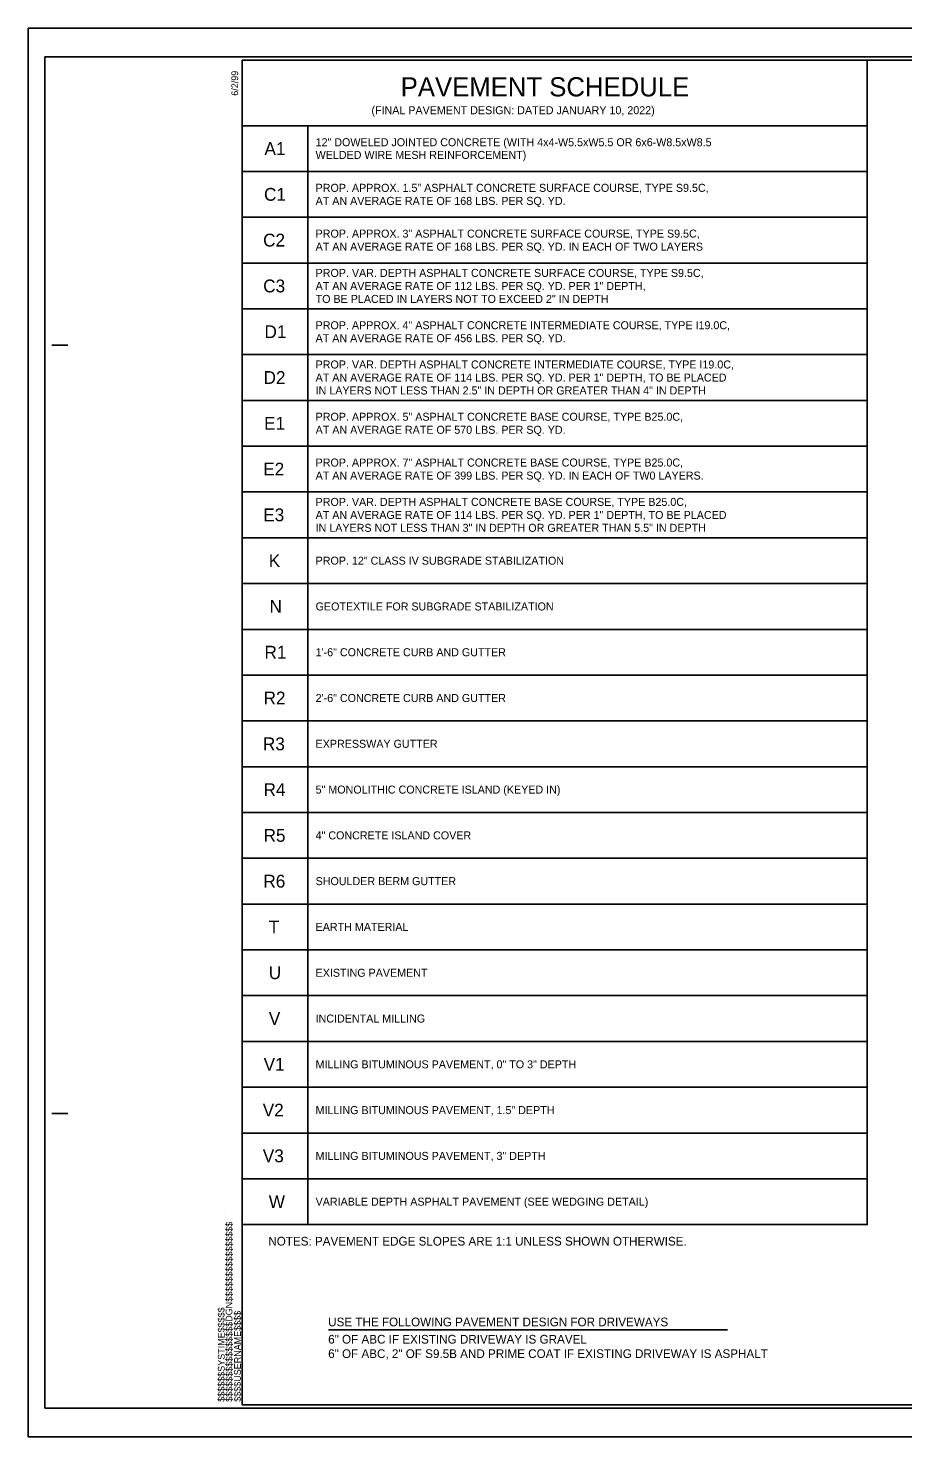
# Model space of a CAD drawing. Extents: x 573748 to 574632, y -54663 to -53209.
# Drawn here: x 573944.2 to 574080.7, y -53428.7 to -53208.7 of the extents above; entities that cross this region are included whole.
import ezdxf

# ---------------------------------------------------------------- set-up
doc = ezdxf.new("R2010")
doc.units = 0
for name, color, linetype in [('Prop Dimension', 7, 'Continuous'), ('Prop Pavement Schedule Description CELL', 7, 'Continuous'), ('Sheet Cutting Line CELL', 7, 'Continuous'), ('Sheet Plot Border Inside CELL', 7, 'Continuous'), ('Sheet Plot Border Outside CELL', 7, 'Continuous'), ('Sheet Typical CELL', 7, 'Continuous')]:
    doc.layers.add(name, color=color, linetype=linetype)

msp = doc.modelspace()

# ---------------------------------------------------------------- linework, layer by layer
at = {"layer": 'Prop Dimension'}
msp.add_line((573991.05, -53412.01), (574053.29, -53412.01), dxfattribs=at)
at = {"layer": 'Prop Pavement Schedule Description CELL'}
msp.add_line((573974.85, -53393.67), (573974.85, -53393.67), dxfattribs=at)
msp.add_lwpolyline([(573977.57, -53213.71), (574075.13, -53213.71), (574075.13, -53223.94), (573977.57, -53223.94)], close=True, dxfattribs=at)
for points in [[(573987.8, -53231.09), (573977.57, -53231.09), (573977.57, -53223.94), (574075.13, -53223.94), (574075.13, -53231.09), (573987.8, -53231.09), (573987.8, -53223.94)], [(573987.8, -53238.24), (573977.57, -53238.24), (573977.57, -53231.09), (574075.13, -53231.09), (574075.13, -53238.24), (573987.8, -53238.24), (573987.8, -53231.09)], [(573987.8, -53245.39), (573977.57, -53245.39), (573977.57, -53238.24), (574075.13, -53238.24), (574075.13, -53245.39), (573987.8, -53245.39), (573987.8, -53238.24)], [(573987.8, -53252.54), (573977.57, -53252.54), (573977.57, -53245.39), (574075.13, -53245.39), (574075.13, -53252.54), (573987.8, -53252.54), (573987.8, -53245.39)], [(573987.8, -53259.69), (573977.57, -53259.69), (573977.57, -53252.54), (574075.13, -53252.54), (574075.13, -53259.69), (573987.8, -53259.69), (573987.8, -53252.54)], [(573987.8, -53266.84), (573977.57, -53266.84), (573977.57, -53259.69), (574075.13, -53259.69), (574075.13, -53266.84), (573987.8, -53266.84), (573987.8, -53259.69)], [(573987.8, -53273.99), (573977.57, -53273.99), (573977.57, -53266.84), (574075.13, -53266.84), (574075.13, -53273.99), (573987.8, -53273.99), (573987.8, -53266.84)], [(573987.8, -53281.14), (573977.57, -53281.14), (573977.57, -53273.99), (574075.13, -53273.99), (574075.13, -53281.14), (573987.8, -53281.14), (573987.8, -53273.99)], [(573987.8, -53288.3), (573977.57, -53288.3), (573977.57, -53281.14), (574075.13, -53281.14), (574075.13, -53288.3), (573987.8, -53288.3), (573987.8, -53281.14)], [(573987.8, -53295.45), (573977.57, -53295.45), (573977.57, -53288.3), (574075.13, -53288.3), (574075.13, -53295.45), (573987.8, -53295.45), (573987.8, -53288.3)], [(573987.8, -53302.6), (573977.57, -53302.6), (573977.57, -53295.45), (574075.13, -53295.45), (574075.13, -53302.6), (573987.8, -53302.6), (573987.8, -53295.45)], [(573987.8, -53309.75), (573977.57, -53309.75), (573977.57, -53302.6), (574075.13, -53302.6), (574075.13, -53309.75), (573987.8, -53309.75), (573987.8, -53302.6)], [(573987.8, -53316.9), (573977.57, -53316.9), (573977.57, -53309.75), (574075.13, -53309.75), (574075.13, -53316.9), (573987.8, -53316.9), (573987.8, -53309.75)], [(573987.8, -53324.05), (573977.57, -53324.05), (573977.57, -53316.9), (574075.13, -53316.9), (574075.13, -53324.05), (573987.8, -53324.05), (573987.8, -53316.9)], [(573987.8, -53331.2), (573977.57, -53331.2), (573977.57, -53324.05), (574075.13, -53324.05), (574075.13, -53331.2), (573987.8, -53331.2), (573987.8, -53324.05)], [(573987.8, -53338.35), (573977.57, -53338.35), (573977.57, -53331.2), (574075.13, -53331.2), (574075.13, -53338.35), (573987.8, -53338.35), (573987.8, -53331.2)], [(573987.8, -53345.5), (573977.57, -53345.5), (573977.57, -53338.35), (574075.13, -53338.35), (574075.13, -53345.5), (573987.8, -53345.5), (573987.8, -53338.35)], [(573987.8, -53352.65), (573977.57, -53352.65), (573977.57, -53345.5), (574075.13, -53345.5), (574075.13, -53352.65), (573987.8, -53352.65), (573987.8, -53345.5)], [(573987.8, -53359.81), (573977.57, -53359.81), (573977.57, -53352.65), (574075.13, -53352.65), (574075.13, -53359.81), (573987.8, -53359.81), (573987.8, -53352.65)], [(573987.8, -53366.96), (573977.57, -53366.96), (573977.57, -53359.81), (574075.13, -53359.81), (574075.13, -53366.96), (573987.8, -53366.96), (573987.8, -53359.81)], [(573987.8, -53374.11), (573977.57, -53374.11), (573977.57, -53366.96), (574075.13, -53366.96), (574075.13, -53374.11), (573987.8, -53374.11), (573987.8, -53366.96)], [(573987.8, -53381.26), (573977.57, -53381.26), (573977.57, -53374.11), (574075.13, -53374.11), (574075.13, -53381.26), (573987.8, -53381.26), (573987.8, -53374.11)], [(573987.8, -53388.41), (573977.57, -53388.41), (573977.57, -53381.26), (574075.13, -53381.26), (574075.13, -53388.41), (573987.8, -53388.41), (573987.8, -53381.26)], [(573987.8, -53395.56), (573977.57, -53395.56), (573977.57, -53388.41), (574075.13, -53388.41), (574075.13, -53395.56), (573987.8, -53395.56), (573987.8, -53388.41)]]:
    msp.add_lwpolyline(points, dxfattribs=at)
at = {"layer": 'Sheet Cutting Line CELL'}
for p, q in [((574280.97, -53208.71), (573944.17, -53208.71)), ((573944.17, -53208.71), (573944.17, -53428.71)), ((573944.17, -53428.71), (574280.97, -53428.71))]:
    msp.add_line(p, q, dxfattribs=at)
at = {"layer": 'Sheet Plot Border Inside CELL'}
msp.add_lwpolyline([(574280.07, -53213.2), (573946.77, -53213.2), (573946.77, -53424.22), (574280.07, -53424.22)], close=True, dxfattribs=at)
at = {"layer": 'Sheet Plot Border Outside CELL'}
msp.add_lwpolyline([(574280.97, -53208.71), (573944.17, -53208.71), (573944.17, -53428.71), (574280.97, -53428.71)], close=True, dxfattribs=at)
at = {"layer": 'Sheet Typical CELL'}
for p, q in [((573947.87, -53258.21), (573950.37, -53258.21)), ((573947.87, -53378.21), (573950.37, -53378.21)), ((573977.57, -53423.71), (573977.57, -53423.71)), ((573977.57, -53423.71), (573977.57, -53423.71)), ((573977.57, -53423.71), (573977.57, -53423.71)), ((573977.57, -53423.71), (573977.57, -53423.71)), ((573977.57, -53423.71), (573977.57, -53423.71)), ((573977.57, -53423.71), (573977.57, -53423.71))]:
    msp.add_line(p, q, dxfattribs=at)
msp.add_lwpolyline([(574277.57, -53213.71), (573977.57, -53213.71), (573977.57, -53423.71), (574277.57, -53423.71)], close=True, dxfattribs=at)
msp.add_lwpolyline([(573985.07, -53423.71), (573985.07, -53423.71)], dxfattribs=at)

# ---------------------------------------------------------------- texts
at = {"layer": 'Prop Pavement Schedule Description CELL'}
for s, height, p in [('PAVEMENT SCHEDULE', 3, (574002.31, -53219.37)), ('(FINAL PAVEMENT DESIGN: DATED JANUARY 10, 2022)', 1.25, (573997.74, -53222.15)), ('A1', 2, (573981.05, -53228.51)), ('12" DOWELED JOINTED CONCRETE (WITH 4x4-W5.5xW5.5 OR 6x6-W8.5xW8.5', 1.25, (573989.03, -53227.15)), ('WELDED WIRE MESH REINFORCEMENT)', 1.25, (573989.03, -53229.13)), ('PROP. APPROX. 1.5" ASPHALT CONCRETE SURFACE COURSE, TYPE S9.5C, ', 1.25, (573989.03, -53234.27)), ('C1', 2, (573980.98, -53235.66)), ('AT AN AVERAGE RATE OF 168 LBS. PER SQ. YD.', 1.25, (573989.03, -53236.31)), ('C2', 2, (573980.84, -53242.81)), ('AT AN AVERAGE RATE OF 168 LBS. PER SQ. YD. IN EACH OF TWO LAYERS', 1.25, (573989.03, -53243.46)), ('PROP. APPROX. 3" ASPHALT CONCRETE SURFACE COURSE, TYPE S9.5C, ', 1.25, (573989.03, -53241.42)), ('PROP. VAR. DEPTH ASPHALT CONCRETE SURFACE COURSE, TYPE S9.5C, ', 1.25, (573989.03, -53247.56)), ('C3', 2, (573980.85, -53249.97)), ('AT AN AVERAGE RATE OF 112 LBS. PER SQ. YD. PER 1" DEPTH,', 1.25, (573989.03, -53249.6)), ('TO BE PLACED IN LAYERS NOT TO EXCEED 2" IN DEPTH', 1.25, (573989.03, -53251.62)), ('D1', 2, (573981.05, -53257.12)), ('PROP. APPROX. 4" ASPHALT CONCRETE INTERMEDIATE COURSE, TYPE I19.0C,', 1.25, (573989.03, -53255.73)), ('AT AN AVERAGE RATE OF 456 LBS. PER SQ. YD.', 1.25, (573989.03, -53257.75)), ('PROP. VAR. DEPTH ASPHALT CONCRETE INTERMEDIATE COURSE, TYPE I19.0C, ', 1.25, (573989.03, -53261.86)), ('D2', 2, (573980.91, -53264.27)), ('AT AN AVERAGE RATE OF 114 LBS. PER SQ. YD. PER 1" DEPTH, TO BE PLACED', 1.25, (573989.03, -53263.9)), ('IN LAYERS NOT LESS THAN 2.5" IN DEPTH OR GREATER THAN 4" IN DEPTH', 1.25, (573989.03, -53265.92)), ('E1', 2, (573980.99, -53271.42)), ('AT AN AVERAGE RATE OF 570 LBS. PER SQ. YD.', 1.25, (573989.03, -53272.06)), ('PROP. APPROX. 5" ASPHALT CONCRETE BASE COURSE, TYPE B25.0C,', 1.25, (573989.03, -53270.02)), ('E2', 2, (573980.85, -53278.57)), ('PROP. APPROX. 7" ASPHALT CONCRETE BASE COURSE, TYPE B25.0C,', 1.25, (573989.03, -53277.17)), ('AT AN AVERAGE RATE OF 399 LBS. PER SQ. YD. IN EACH OF TW0 LAYERS.', 1.25, (573989.03, -53279.21)), ('E3', 2, (573980.86, -53285.72)), ('PROP. VAR. DEPTH ASPHALT CONCRETE BASE COURSE, TYPE B25.0C, ', 1.25, (573989.03, -53283.32)), ('AT AN AVERAGE RATE OF 114 LBS. PER SQ. YD. PER 1" DEPTH, TO BE PLACED', 1.25, (573989.03, -53285.36)), ('IN LAYERS NOT LESS THAN 3" IN DEPTH OR GREATER THAN 5.5" IN DEPTH', 1.25, (573989.03, -53287.37)), ('K', 2, (573981.72, -53292.87)), ('PROP. 12" CLASS IV SUBGRADE STABILIZATION', 1.25, (573989.03, -53292.5)), ('N', 2, (573981.84, -53300.02)), ('GEOTEXTILE FOR SUBGRADE STABILIZATION', 1.25, (573989.03, -53299.65)), ('R1', 2, (573981.05, -53307.17)), ('1\'-6" CONCRETE CURB AND GUTTER', 1.25, (573989.03, -53306.8)), ('R2', 2, (573980.91, -53314.32)), ('2\'-6" CONCRETE CURB AND GUTTER', 1.25, (573989.03, -53313.95)), ('R3', 2, (573980.81, -53321.48)), ('EXPRESSWAY GUTTER', 1.25, (573989.03, -53321.1)), ('R4', 2, (573980.9, -53328.63)), ('5" MONOLITHIC CONCRETE ISLAND (KEYED IN)', 1.25, (573989.03, -53328.25)), ('R5', 2, (573980.91, -53335.78)), ('4" CONCRETE ISLAND COVER', 1.25, (573989.03, -53335.4)), ('R6', 2, (573980.88, -53342.93)), ('SHOULDER BERM GUTTER', 1.25, (573989.03, -53342.55)), ('T', 2, (573981.72, -53350.08)), ('EARTH MATERIAL', 1.25, (573989.03, -53349.7)), ('U', 2, (573981.72, -53357.23)), ('EXISTING PAVEMENT', 1.25, (573989.03, -53356.86)), ('V', 2, (573981.73, -53364.38)), ('INCIDENTAL MILLING', 1.25, (573989.03, -53364.01)), ('V1', 2, (573980.92, -53371.53)), ('MILLING BITUMINOUS PAVEMENT, 0" TO 3" DEPTH', 1.25, (573989.03, -53371.16)), ('V2', 2, (573980.78, -53378.68)), ('MILLING BITUMINOUS PAVEMENT, 1.5" DEPTH', 1.25, (573989.03, -53378.31)), ('V3', 2, (573980.79, -53385.83)), ('MILLING BITUMINOUS PAVEMENT, 3" DEPTH', 1.25, (573989.03, -53385.46)), ('W', 2, (573981.72, -53392.99)), ('VARIABLE DEPTH ASPHALT PAVEMENT (SEE WEDGING DETAIL)', 1.25, (573989.03, -53392.61)), ('NOTES: PAVEMENT EDGE SLOPES ARE 1:1 UNLESS SHOWN OTHERWISE.', 1.3604, (573981.65, -53398.84)), ('USE THE FOLLOWING PAVEMENT DESIGN FOR DRIVEWAYS      ', 1.3604, (573990.99, -53411.45)), ('6" OF ABC IF EXISTING DRIVEWAY IS GRAVEL', 1.3604, (573990.99, -53414.15)), ('6" OF ABC, 2" OF S9.5B AND PRIME COAT IF EXISTING DRIVEWAY IS ASPHALT        ', 1.3604, (573990.99, -53416.4))]:
    msp.add_text(s, height=height, dxfattribs=at).set_placement(p)
at = {"layer": 'Sheet Typical CELL'}
for s, p in [('6/2/99', (573976.94, -53219.26)), ('$$$$$$$$$$$$$$$$DGN$$$$$$$$$$$$$$$$', (573976.04, -53423.24)), ('$$$$$$SYSTIME$$$$$', (573974.83, -53423.24)), ('$$$$USERNAME$$$$', (573977.36, -53423.23))]:
    msp.add_text(s, height=1.05, rotation=90, dxfattribs=at).set_placement(p)

doc.saveas('drawing.dxf')
